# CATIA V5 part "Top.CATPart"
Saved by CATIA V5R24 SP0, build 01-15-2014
Part number: Part1.1
Bounding box of the stored display mesh (mm): x -50 to 50, y -25 to 25, z -20 to 0
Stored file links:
  D:\KAVITA\CATIA V5-6R2014 Project_ Kavita\CATIA V5-6R2014_partfiles\Partfiles\c12_catia_v5-6r2014_prt\c12_catia_v5r21figr_12-8\Top.CATPart
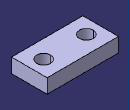
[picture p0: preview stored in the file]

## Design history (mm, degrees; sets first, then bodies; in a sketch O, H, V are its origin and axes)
Body1 (main body)
  Sketch1 on xy-plane, origin (0, 0, 0), H (1, 0, 0), V (0, 1, 0)
    line L1 (50, 25) -> (50, -25)
    line L2 (50, -25) -> (-50, -25)
    line L3 (-50, -25) -> (-50, 25)
    line L4 (-50, 25) -> (50, 25)
    circle A1 centre (-30, 0) radius 10
    point P5 (-30, 0)
    circle A2 centre (30, 0) radius 10
    length L2 = 100
    length L1 = 50
    radius A1 = 10
    distance P5 V = 30
    vertical: L1 V, L3 V
    horizontal: L2 H, L4 H
    equidistance: L1 L3 O, L2 L4 O
    coincidence: P5 H
    symmetry: A1 A2 V
  Pad1: profile Sketch1, direction (0, 0, -1), length 20
  Sketch2 on face of Pad1, origin (0, 0, 0), H (1, 0, 0), V (0, 1, 0)
  Pad2: profile Sketch2, direction (0, 0, 1), length 10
